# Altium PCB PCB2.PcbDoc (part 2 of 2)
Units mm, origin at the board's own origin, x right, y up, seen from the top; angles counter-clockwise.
Board outline 153.67 x 113.03 mm, 4 copper layers (Top Layer, Mid Layer 1, Mid Layer 2, Bottom Layer), stack 1.57 mm thick; 123 components, 293 nets, 917 pads, 135 vias.
Unrouted connection lines stored in the file: 517.
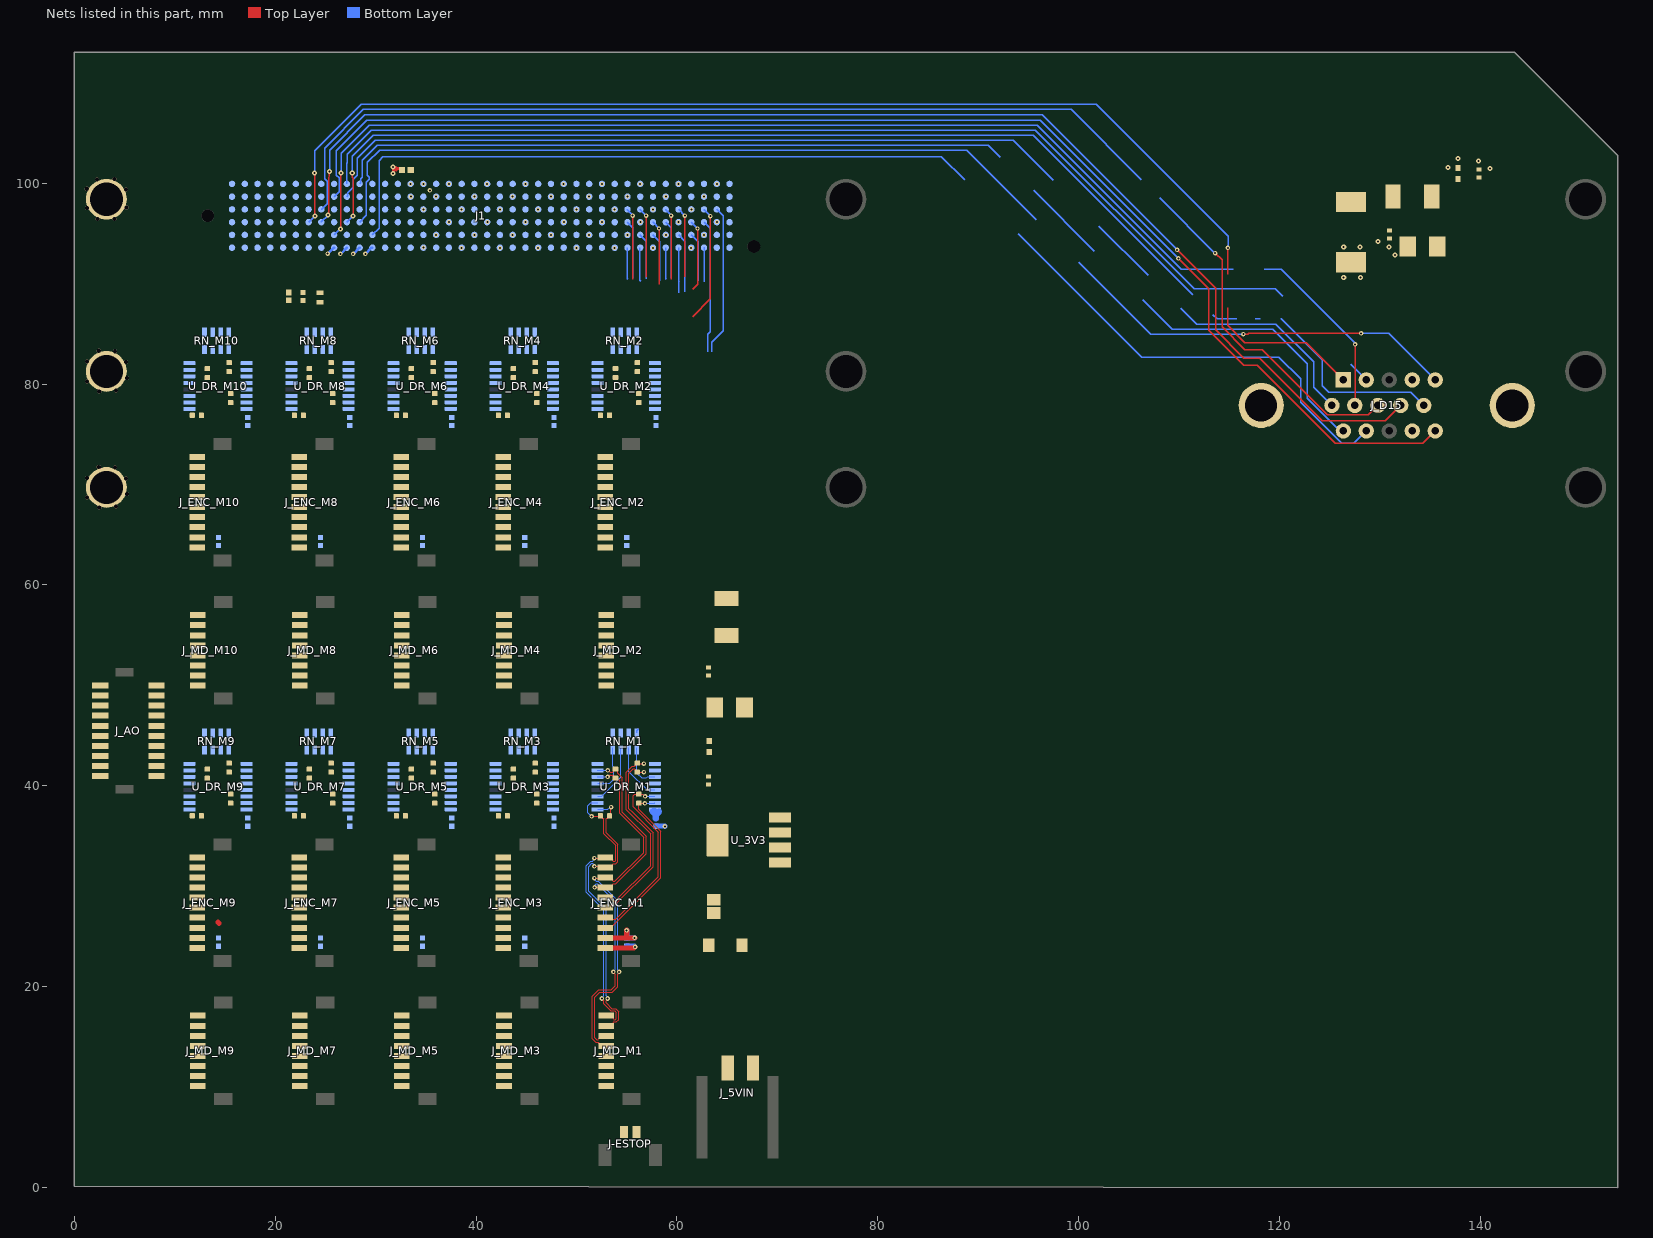
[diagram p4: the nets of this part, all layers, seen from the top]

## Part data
C1: library part CMP-2000-07305-1, "Low ESR, 330 uF, 6.3 V, +/- 10%, -55 to 125 degC, 2-Pin SMD, RoHS, Tape and Reel", Capacitance=330000000pF, Case Code=D, Case Style=Molded, Manufacturer=AVX, Operating Temp Range=-55Cto125C, Package / Case=7343-31, Package Description="2-Pin Surface Mount Device, Body 7.3 x 4.35 mm", Package Reference=CAPMP7344X31-T, Tolerance (+ or -)=10%, Voltage=6.3VDC
C2: library part CMP-2008-04549-2, "Chip Multilayer Ceramic Capacitors for General Purpose, 0402, 4.7uF, X5R, 15%, 20%, 6.3V", Capacitance=4.7uF, Case Code (Imperial)=0402, Case Code (Metric)=1005, Dielectric=X5R, Max Operating Temperature=85°C, Min Operating Temperature=-55°C, Package Quantity=10000, Tolerance=20%, Voltage=6.3V
C5_1: library part CMP-2008-02081-2, "CAP CER 1UF 10V X5R 0402", Capacitance=1uF, Case Code (Imperial)=0402, Case Code (Metric)=1005, Dielectric=X5R, Dielectric Material=Ceramic, Max Operating Temperature=85°C, Min Operating Temperature=-55°C, Package Quantity=1, Tolerance=10%, Voltage=10V
C5_2: library part CMP-13271-000002-1, "CAP CER 10UF 10V X5R 0402", Capacitance=10uF, Manufacturer=Samsung, Temperature="-55°C to +85°C", Temperature Characteristic=X5R, Temperature Coefficient=15%, Temperature Range High=+85°C, Temperature Range Low=-55°C, Tolerance=20%, Voltage Rating=10V
C5_3: library part CMP-2008-02743-1, Manufacturer="AVX Interconnect / Elco"
C10 C11 C50 C51: library part CMP-2100-03641-2, "CAP CER 0.1UF 16V X7R 0402", Capacitance=0.10μF, Manufacturer=Murata, Package=GRM15, Temperature="-55°C to +125°C", Temperature Characteristic=X7R, Temperature Range High=+125°C, Temperature Range Low=-55°C, Tolerance=10%, Voltage Rating=16Vdc
C12 C52: library part CMP-1662-00011-2, "Chip Capacitor, 100 uF, +/- 20%, 6.3 V, -55 to 85 degC, 1206 (3216 Metric), RoHS, Tape and Reel", Capacitance="100 uF", Case Code (Imperial)=1206, Case Code (Metric)=3216, Max Operating Temperature="85 degC", Min Operating Temperature="-55 degC", Package Quantity=2000, Tolerance=20%, Type (Capacitors)=X5R, Voltage Rating="6.3 V"
C13 C53: library part CMP-2008-02797-2, "General Purpose Ceramic Capacitor, 0402, 10nF, 10%, X7R, 15%, 16V", Capacitance=10nF, Case Code (Imperial)=0402, Case Code (Metric)=1005, Dielectric=X7R, Insulation Resistance=100GR, Max Operating Temperature=125°C, Min Operating Temperature=-55°C, Package Quantity=1, Tolerance=10%, Voltage=16V
C60: library part CMP-08246-002634-1, "CAP CER 68UF 10V X5R 1206", Capacitance=68uF, Case Code (Imperial)=1206, Case Code (Metric)=3216, Dielectric=X5R, Dielectric Material=Ceramic, Max Operating Temperature=85°C, Min Operating Temperature=-55°C, Package Quantity=2000, Tolerance=20%, Voltage Rating=10V
C61: library part CMP-08246-003796-1, "Multilayer Ceramic Capacitors 33μF ±20% 6.3V X5R SMD 0805", Capacitance=33uF, Case Code (Imperial)=0805, Case Code (Metric)=2012, Dielectric=X5R, Dielectric Material=Ceramic, Max Operating Temperature=85°C, Min Operating Temperature=-55°C, Package Quantity=1, Tolerance=20%, Voltage Rating=6.3V
CP1_M1 CP1_M2 CP1_M3 CP1_M4 CP1_M5 CP1_M6 CP1_M7 CP1_M8 CP1_M9 CP1_M10 CP2_M1 CP2_M2 CP2_M3 CP2_M4 CP2_M5 CP2_M6 CP2_M7 CP2_M8 CP2_M9 CP2_M10: library part CMP-2008-02046-2, "CAP CER 0.1UF 10V X5R 0402", Capacitance="0.10 μF", Manufacturer=Kemet, Package=C0402-BB, Temperature="-55°C to +125°C", Temperature Characteristic=X5R, Temperature Coefficient=15%, Temperature Range High=+125°C, Temperature Range Low=-55°C, Tolerance=0.1, Voltage Rating="10 V"
J1: library part CMP-02761-000136-1, "CONN HD ARRAY PLUG 240P SMD GOLD", Contact Resistance=5.5mR, Housing Color=Black, Max Current Rating=2.3A, Max Operating Temperature=125°C, Max Voltage Rating (AC)=240V, Min Operating Temperature=-55°C
J-ESTOP: library part CMP-04776-000017-1, "CONN HEADER SMD R/A 2POS 1.25MM", Ambient Temperature Range High=+105°C, Ambient Temperature Range Low=-40°C, Current Rating=1.5A, Manufacturer=Molex, Package=HDR2, Temperature="-40°C to +105°C", Voltage Rating=50V
J_5VIN: "No Description Available", Mfr_Name="Molex Connector Corporation"
J_AO: library part CMP-04776-000294-1, "CONN HEADER SMD 20POS 1MM", Color=Natural, Contact Resistance=20mR, Current Rating=1A, Max Operating Temperature=85°C, Min Operating Temperature=-40°C, Package Quantity=1100, Voltage Rating=50V
J_D15: library part "D-Sub 15 Male-2"
J_ENC_M1 J_ENC_M2 J_ENC_M3 J_ENC_M4 J_ENC_M5 J_ENC_M6 J_ENC_M7 J_ENC_M8 J_ENC_M9 J_ENC_M10: library part CMP-003-000001-2, "No Description Available", Mfr_Name="Molex Connector Corporation"
J_MD_M1 J_MD_M2 J_MD_M3 J_MD_M4 J_MD_M5 J_MD_M6 J_MD_M7 J_MD_M8 J_MD_M9 J_MD_M10: library part CMP-005-000000-1, "No Description Available", Mfr_Name="Molex Connector Corporation"
L10 L50: library part CMP-1353-00039-1, "SMD Power Inductor WE-LHMI, L=6.8 µH", Inductance="6.8 ÂµH", Manufacturer="Wuerth Elektronik"
R1_M1 R1_M2 R1_M3 R1_M4 R1_M5 R1_M6 R1_M7 R1_M8 R1_M9 R1_M10 R2_M1 R2_M2 R2_M3 R2_M4 R2_M5 R2_M6 R2_M7 R2_M8 R2_M9 R2_M10 R3_M1 R3_M2 R3_M3 R3_M4 R3_M5 R3_M6 R3_M7 R3_M8 R3_M9 R3_M10 R4_M1 R4_M2 R4_M3 R4_M4 R4_M5 R4_M6 R4_M7 R4_M8 R4_M9 R4_M10: library part CMP-009-00167-3, "Chip Resistor, 100 Ohms, +/-1 %, 63 mW, -55 to 155 degC, 0402", Case/Package=0402, Max Operating Temperature=155°C, Min Operating Temperature=-55°C, Power=63mW, Tolerance=1%
RN_M1 RN_M2 RN_M3 RN_M4 RN_M5 RN_M6 RN_M7 RN_M8 RN_M9 RN_M10: library part CMP-06828-000004-1, "RES ARRAY 4 RES 47 OHM 1206", Case/Package=Molded, Max Operating Temperature=125°C, Min Operating Temperature=-55°C, Number of Resistors=4, Package Quantity=5000, Power Dissipation=63mW, Resistance=47R, Temperature Coefficient=200ppm/°C, Tolerance=5%, Working Voltage=50V
U_3V3: library part CMP-0062-01662-3, "1.5A Fast Ultra Low Dropout Linear Regulator, 5-pin SOT-223, Pb-Free", Manufacturer="Texas Instruments", PackageTopMarking=XYTT*LBEB, PowerWise=N
U_DR_M1 U_DR_M2 U_DR_M3 U_DR_M4 U_DR_M5 U_DR_M6 U_DR_M7 U_DR_M8 U_DR_M9 U_DR_M10: library part CMP-0310-00537-3, "Low-Voltage High-Speed Quadruple Differential Line Receiver with +/-15-kV IEC ESD, 0 TX / 4 RX, 3.3V, -40 to 85 degC, 16-Pin TSSOP (PW), Green(RoHS & no Sb/Br)", Manufacturer="Texas Instruments", Rating=Catalog, Receivers Per Package=4, Supply Voltage(s)(Max)(V)=3.6, Supply Voltage(s)(Min)(V)=3, Supply Voltage(s)(V)=3.3

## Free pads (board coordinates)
  round 4.064 hole 3.3: " "(3.2,69.7) " "(3.2,81.26) " "(3.2,98.4) " "(76.835,69.7) " "(76.835,81.26) " "(76.835,98.4) " "(150.47,69.7) " "(150.47,81.26) " "(150.47,98.4)

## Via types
v1: diameter 0.4, hole 0.2, Top Layer to Bottom Layer, 52 vias
v2: diameter 0.45, hole 0.2, Top Layer to Bottom Layer, 38 vias
v3: diameter 0.4, hole 0.4, Top Layer to Bottom Layer, 24 vias
v4: diameter 0.5, hole 0.2, Top Layer to Bottom Layer, 21 vias

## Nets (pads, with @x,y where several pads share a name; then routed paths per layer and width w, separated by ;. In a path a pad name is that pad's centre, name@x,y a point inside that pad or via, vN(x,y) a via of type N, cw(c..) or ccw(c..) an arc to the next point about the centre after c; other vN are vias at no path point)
3.3V_EXT: C61.1 CP2_M1.1 CP2_M2.1 CP2_M3.1 CP2_M4.1 CP2_M5.1 CP2_M6.1 CP2_M7.1 CP2_M8.1 CP2_M9.1 CP2_M10.1 U_3V3.3 U_3V3.4 U_DR_M1.16 U_DR_M2.16 U_DR_M3.16 U_DR_M4.16 U_DR_M5.16 U_DR_M6.16 U_DR_M7.16 U_DR_M8.16 U_DR_M9.16 U_DR_M10.16 | length 3.2
  Bottom Layer w0.635: CP2_M1.1@57.912,36.779 57.912,37.135 ; U_DR_M1.16@57.636,37.469 U_DR_M1.16@57.803,37.469 ; U_DR_M1.16@57.636,37.469 U_DR_M1.16@57.803,37.469 ; U_DR_M1.16@57.636,37.469 U_DR_M1.16@57.803,37.469 ; U_DR_M1.16@57.636,37.469 U_DR_M1.16@57.803,37.469 ; U_DR_M1.16@57.636,37.469 57.607,37.44 57.912,37.135 ; 57.912,37.135 58.217,37.44 ; 57.912,37.135 58.217,37.44 ; 57.912,37.135 58.217,37.44 ; 57.912,37.135 58.217,37.44
3.3V_RMC: J1.F8
5V_C_SERIES: C1.1 C2.1 C10.2 J1.A16 J1.B15 L10.1
  other v1: 34.747,99.924
  other v2: 33.503,98.654
5V_EXT: C50.2 J_5VIN.1 L50.1
5V_FILT: C11.2 C12.2 C13.1 J_D15.4 L10.2
5V_M1: C51.2 C52.2 C53.1 C60.1 CP1_M1.1 CP1_M2.1 CP1_M3.1 CP1_M4.1 CP1_M5.1 CP1_M6.1 CP1_M7.1 CP1_M8.1 CP1_M9.1 CP1_M10.1 J_ENC_M1.9 J_ENC_M2.9 J_ENC_M3.9 J_ENC_M4.9 J_ENC_M5.9 J_ENC_M6.9 J_ENC_M7.9 J_ENC_M8.9 J_ENC_M9.9 J_ENC_M10.9 L50.2 U_3V3.1 U_3V3.2 | length 10.7
  Top Layer w0.508: 14.3,26.416 14.405,26.311 ; 54.026,24.863 J_ENC_M1.9@52.885,24.863 ; v2(55.004,25.616) 55.004,24.917 54.949,24.863 ; v2@55.787,24.863 54.949,24.863 ; v2@55.799,24.851 v2@55.803,24.855 ; J_ENC_M1.9@52.885,24.863 54.949,24.863 ; J_ENC_M1.9@52.885,24.863 54.949,24.863 ; J_ENC_M1.9@52.885,24.863 54.949,24.863
  Bottom Layer w0.508: CP1_M1.1@55.01,24.841 CP1_M1.1@55.016,24.841 ; v2@55.016,25.604 CP1_M1.1@55.016,24.841 ; v2(55.791,24.867) 55.765,24.841 CP1_M1.1@55.016,24.841 ; CP1_M1.1@55.016,24.823 CP1_M1.1@55.016,24.841 ; CP1_M1.1@55.016,24.823 CP1_M1.1@55.016,24.841 ; CP1_M1.1@55.016,24.823 CP1_M1.1@55.022,24.829 ; CP1_M1.1@55.016,24.823 CP1_M1.1@55.022,24.829 ; CP1_M1.1@55.016,24.823 CP1_M1.1@55.022,24.829 ; CP1_M1.1@55.016,24.823 CP1_M1.1@55.016,24.841
5V_RMC: C5_1.1 C5_2.1 C5_3.2 J1.F9 J1.F10 J1.F11 J1.F12 | length 3.6
  Bottom Layer w0.254: v2(25.222,92.989) 25.254,92.989 25.838,93.574 J1.F9@25.87,93.574 ; v2(26.492,92.964) 26.531,92.964 J1.F10@27.14,93.574 ; v2(27.762,92.964) 27.801,92.964 J1.F11@28.41,93.574 ; v2(28.981,92.964) 29.591,93.574 J1.F12@29.68,93.574
A1: J1.C39 RN_M1.8 | length 16.5
  Bottom Layer w0.142: RN_M1.8@56.007,45.276 RN_M1.8@56.007,45.49 ; RN_M1.8@56.161,45.644 RN_M1.8@56.007,45.49 ; RN_M1.8@56.161,45.655 56.007,45.5 RN_M1.8@56.007,45.49 ; 63.475,83.219 63.475,84.176 64.605,85.306 64.605,89.027 64.605,96.749 ; 64.605,96.749 J1.C39@63.97,97.384 64.605,96.749
A2: J1.C38 RN_M2.8 | length 11.7
  Top Layer w0.142: 61.567,86.713 63.322,88.468 63.322,91.275 63.322,96.215 v2(63.322,96.723)
  Bottom Layer w0.142: J1.C38@62.624,97.308 J1.C38@62.624,97.314 ; J1.C38@62.7,97.384 62.7,97.364 63.322,96.743 v2(63.322,96.723)
A3: J1.C36 RN_M3.8 | length 7
  Top Layer w0.142: 60.757,90.678 60.782,90.703 v2(60.782,96.761)
  Bottom Layer w0.142: J1.C36@60.16,97.384 v2(60.782,96.761)
A4: J1.C35 RN_M4.8 | length 7.2
  Top Layer w0.142: 59.436,90.424 v2(59.436,96.774)
  Bottom Layer w0.142: J1.C35@58.89,97.384 58.89,97.352 59.436,96.806 v2(59.436,96.774)
A5: J1.C33 RN_M5.8 | length 9.6
  Top Layer w0.142: 56.921,90.678 56.947,90.703 v2(56.947,96.761)
  Bottom Layer w0.142: J1.C33@56.325,97.383 v2(56.947,96.761) ; J1.C33@56.325,97.383 v2(56.947,96.761) ; J1.C33@56.325,97.383 v2(56.947,96.761) ; J1.C33@56.325,97.383 v2(56.947,96.761)
A6: J1.C30 RN_M6.8
A7: J1.C32 RN_M7.8 | length 7.3
  Top Layer w0.142: 55.601,90.424 v2(55.601,96.774)
  Bottom Layer w0.142: v2(55.601,96.774) 55.601,96.806 J1.C32@55.055,97.352 ; J1.C32@55.055,97.352 J1.C32@55.055,97.384 ; J1.C32@55.055,97.352 J1.C32@55.055,97.384 ; J1.C32@55.055,97.352 J1.C32@55.055,97.384 ; J1.C32@55.055,97.352 J1.C32@55.055,97.384
A8: J1.C29 RN_M8.8
A9: J1.C27 RN_M9.8
A10: J1.C26 RN_M10.8
A_M1_N: J_ENC_M1.6 R3_M1.2 U_DR_M1.9 | length 18.7
  Top Layer w0.114: J_ENC_M1.6@52.897,27.851 J_ENC_M1.6@53.372,27.851 ; J_ENC_M1.6@53.36,27.863 J_ENC_M1.6@53.603,28.106 ; 53.603,28.175 J_ENC_M1.6@53.603,28.106 ; 53.924,28.242 57.62,31.939 57.62,35.329 55.53,37.42 55.213,37.737 55.213,41.237 55.656,41.68 55.773,41.68 55.843,41.61 55.843,41.544 56.036,41.351 R3_M1.2@56.058,41.351 ; 53.936,28.23 53.682,28.23 53.615,28.163 J_ENC_M1.6@53.603,28.106 ; R3_M1.2@56.07,41.364 v2(56.718,41.364) ; R3_M1.2@56.07,41.339 R3_M1.2@56.082,41.352 ; R3_M1.2@56.07,41.339 R3_M1.2@56.082,41.352 ; R3_M1.2@56.07,41.339 R3_M1.2@56.082,41.352 ; R3_M1.2@56.07,41.339 R3_M1.2@56.082,41.352
A_M1_P: J_ENC_M1.5 R3_M1.1 U_DR_M1.10 | length 18.6
  Top Layer w0.114: J_ENC_M1.5@52.897,28.851 J_ENC_M1.5@53.372,28.851 ; J_ENC_M1.5@53.36,28.863 J_ENC_M1.5@53.372,28.851 ; 53.67,28.484 53.824,28.484 57.379,32.039 57.379,35.229 54.971,37.637 54.971,41.337 55.556,41.922 55.773,41.922 55.843,41.992 55.843,42.059 56.036,42.251 R3_M1.1@56.058,42.251 ; 53.682,28.472 53.615,28.539 53.603,28.551 53.603,28.62 J_ENC_M1.5@53.372,28.851 ; R3_M1.1@56.07,42.239 R3_M1.1@56.119,42.19 ; R3_M1.1@56.107,42.202 v2(56.706,42.202)
A_M2_N: J_ENC_M2.6 R3_M2.2 U_DR_M2.9
A_M2_P: J_ENC_M2.5 R3_M2.1 U_DR_M2.10
A_M3_N: J_ENC_M3.6 R3_M3.2 U_DR_M3.9
A_M3_P: J_ENC_M3.5 R3_M3.1 U_DR_M3.10
A_M4_N: J_ENC_M4.6 R3_M4.2 U_DR_M4.9
A_M4_P: J_ENC_M4.5 R3_M4.1 U_DR_M4.10
A_M5_N: J_ENC_M5.6 R3_M5.2 U_DR_M5.9
A_M5_P: J_ENC_M5.5 R3_M5.1 U_DR_M5.10
A_M6_N: J_ENC_M6.6 R3_M6.2 U_DR_M6.9
A_M6_P: J_ENC_M6.5 R3_M6.1 U_DR_M6.10
A_M7_N: J_ENC_M7.6 R3_M7.2 U_DR_M7.9
A_M7_P: J_ENC_M7.5 R3_M7.1 U_DR_M7.10
A_M8_N: J_ENC_M8.6 R3_M8.2 U_DR_M8.9
A_M8_P: J_ENC_M8.5 R3_M8.1 U_DR_M8.10
A_M9_N: J_ENC_M9.6 R3_M9.2 U_DR_M9.9
A_M9_P: J_ENC_M9.5 R3_M9.1 U_DR_M9.10
A_M10_N: J_ENC_M10.6 R3_M10.2 U_DR_M10.9
A_M10_P: J_ENC_M10.5 R3_M10.1 U_DR_M10.10
AGND: J_AO.1 J_AO.2 J_AO.3 J_AO.4 J_AO.5 J_AO.6 J_AO.7 J_AO.8 J_AO.9 J_AO.10
AGND_M1: J_MD_M1.8 J_MD_M2.8 J_MD_M3.8 J_MD_M4.8 J_MD_M5.8 J_MD_M6.8 J_MD_M7.8 J_MD_M8.8 J_MD_M9.8 J_MD_M10.8
ANA1: J_AO.12 J_MD_M1.7
ANA2: J_AO.11 J_MD_M2.7
ANA3: J_AO.14 J_MD_M3.7
ANA4: J_AO.13 J_MD_M4.7
ANA5: J_AO.16 J_MD_M5.7
ANA6: J_AO.15 J_MD_M6.7
ANA7: J_AO.18 J_MD_M7.7
ANA8: J_AO.17 J_MD_M8.7
ANA9: J_AO.20 J_MD_M9.7
ANA10: J_AO.19 J_MD_M10.7
B1: J1.D38 RN_M1.7 | length 13.3
  Bottom Layer w0.142: J1.D38@62.7,96.114 63.309,95.505 63.309,85.395 63.309,85.179 63.068,84.938 63.068,83.21
B2: J1.D37 RN_M2.7 | length 7.1
  Top Layer w0.142: 61.582,89.459 62.065,89.941 v1(62.065,95.479)
  Bottom Layer w0.142: J1.D37@61.43,96.114 v1(62.065,95.479)
B3: J1.D35 RN_M3.7 | length 5.8
  Bottom Layer w0.142: J1.D35@58.89,96.114 59.436,95.568 59.436,90.551
B4: J1.D34 RN_M4.7 | length 6.6
  Top Layer w0.142: 58.229,89.941 v1(58.229,95.479)
  Bottom Layer w0.142: J1.D34@57.62,96.082 J1.D34@57.62,96.088 ; J1.D34@57.62,96.114 J1.D34@57.62,96.088 ; v1(58.229,95.479) J1.D34@57.62,96.088 ; J1.D34@57.595,96.113 J1.D34@57.62,96.088 ; J1.D34@57.595,96.113 J1.D34@57.62,96.088 ; J1.D34@57.595,96.113 J1.D34@57.62,96.088 ; J1.D34@57.595,96.113 J1.D34@57.62,96.088
B5: J1.D32 RN_M5.7 | length 8.1
  Bottom Layer w0.142: 55.601,90.551 55.601,95.568 ; J1.D32@55.055,96.114 55.601,95.568 ; J1.D32@55.055,96.114 55.601,95.568 ; J1.D32@55.055,96.114 55.601,95.568 ; J1.D32@55.055,96.114 55.601,95.568
B6: J1.D31 RN_M6.7
B7: J1.D29 RN_M7.7
B8: J1.D28 RN_M8.7
B9: J1.D26 RN_M9.7
B10: J1.D25 RN_M10.7
B_M1_N: J_ENC_M1.8 R4_M1.2 U_DR_M1.15 | length 17.5
  Top Layer w0.114: J_ENC_M1.8@52.885,25.863 53.128,26.106 53.651,26.106 58.408,30.863 58.408,35.477 56.21,37.674 R4_M1.2@56.21,38.267 56.225,38.252 v2(56.82,38.252)
  Bottom Layer w0.114: v2(56.82,38.252) 56.839,38.272 57.784,38.272 U_DR_M1.15@57.803,38.291
B_M1_P: J_ENC_M1.7 R4_M1.1 U_DR_M1.14 | length 18.5
  Top Layer w0.114: J_ENC_M1.7@52.885,26.863 53.061,26.687 53.891,26.687 58.166,30.963 58.166,35.377 55.651,37.891 55.651,39.014 55.804,39.167 R4_M1.1@56.21,39.167 56.617,39.167 v2(56.845,38.938)
  Bottom Layer w0.114: v2(56.845,38.938) 56.847,38.94 57.801,38.94 U_DR_M1.14@57.803,38.941
B_M2_N: J_ENC_M2.8 R4_M2.2 U_DR_M2.15
B_M2_P: J_ENC_M2.7 R4_M2.1 U_DR_M2.14
B_M3_N: J_ENC_M3.8 R4_M3.2 U_DR_M3.15
B_M3_P: J_ENC_M3.7 R4_M3.1 U_DR_M3.14
B_M4_N: J_ENC_M4.8 R4_M4.2 U_DR_M4.15
B_M4_P: J_ENC_M4.7 R4_M4.1 U_DR_M4.14
B_M5_N: J_ENC_M5.8 R4_M5.2 U_DR_M5.15
B_M5_P: J_ENC_M5.7 R4_M5.1 U_DR_M5.14
B_M6_N: J_ENC_M6.8 R4_M6.2 U_DR_M6.15
B_M6_P: J_ENC_M6.7 R4_M6.1 U_DR_M6.14
B_M7_N: J_ENC_M7.8 R4_M7.2 U_DR_M7.15
B_M7_P: J_ENC_M7.7 R4_M7.1 U_DR_M7.14
B_M8_N: J_ENC_M8.8 R4_M8.2 U_DR_M8.15
B_M8_P: J_ENC_M8.7 R4_M8.1 U_DR_M8.14
B_M9_N: J_ENC_M9.8 R4_M9.2 U_DR_M9.15
B_M9_P: J_ENC_M9.7 R4_M9.1 U_DR_M9.14
B_M10_N: J_ENC_M10.8 R4_M10.2 U_DR_M10.15
B_M10_P: J_ENC_M10.7 R4_M10.1 U_DR_M10.14
CVRT_DIO3: J1.D8 J_D15.9 | length 131.3
  Top Layer w0.142: v4(25.265,96.85) 25.32,96.905 25.32,100.609 25.39,100.68 25.39,101.105 v4(25.428,101.143) ; v2(109.804,93.345) 113.64,89.51 113.64,85.395 116.459,82.575 118.008,82.575 124.257,76.327 130.524,76.327 J_D15.9@132.067,77.87
  Bottom Layer w0.142: J1.D8@24.6,96.114 24.6,96.15 25.265,96.814 v4(25.265,96.85) ; v4(25.428,101.143) 25.428,103.28 28.936,106.788 96.362,106.788 v2(109.804,93.345)
D15_P1: J1.D7 J_D15.1 | length 125.1
  Top Layer w0.142: v4(23.927,100.99) 23.952,100.965 23.952,96.774 v4(23.978,96.749) ; 114.833,87.605 114.833,85.831 116.54,84.125 122.637,84.125 J_D15.1@126.352,80.41 ; 114.833,90.932 114.833,93.523 v2(114.859,93.548)
  Bottom Layer w0.142: J1.D7@23.33,96.114 23.337,96.114 23.972,96.749 v4(23.978,96.749) ; v4(23.927,100.99) 23.927,103.219 28.561,107.852 101.774,107.852 106.934,102.692 114.892,94.734 114.892,93.582 v2(114.859,93.548)
D15_P2: J1.A10 J_D15.2 | length 106.2
  Bottom Layer w0.142: J1.A10@27.14,99.924 27.14,101.981 27.175,102.016 27.175,102.895 29.56,105.28 95.686,105.28 111.482,89.484 119.564,89.484 120.313,88.735 ; 127.079,81.969 J_D15.2@128.638,80.41
D15_P5: J1.D11 J_D15.5 | length 116.8
  Top Layer w0.142: v2(116.407,84.968) 116.845,84.968 116.915,85.039 v2(128.118,85.039)
  Bottom Layer w0.142: J1.D11@28.41,96.114 29.083,96.786 29.083,100.101 29.362,100.381 29.362,100.585 29.185,100.763 29.185,102.063 30.393,103.271 88.855,103.271 95.771,96.355 ; 99.987,92.138 107.168,84.957 116.396,84.957 v2(116.407,84.968) ; v2(128.118,85.039) 130.886,85.039 135.496,80.429 J_D15.5@135.496,80.41
D15_P6: J1.B10 J_D15.6 | length 103.4
  Bottom Layer w0.142: J1.B10@27.14,98.654 27.228,98.741 27.228,99.036 27.762,99.57 27.762,100.39 28.18,100.808 28.18,102.479 29.976,104.276 93.463,104.276 97.447,100.292 ; 102.019,95.72 106.934,90.805 ; 110.185,87.554 111.766,85.973 119.64,85.973 123.419,82.194 123.419,79.66 J_D15.6@125.209,77.87
D15_P7: J1.E9 J_D15.7 | length 122.7
  Top Layer w0.142: v4(26.492,95.453) 26.53,95.491 26.53,100.978 v4(26.568,101.016) ; J_D15.7@127.495,77.87 127.514,77.889 127.514,83.928 v2(127.533,83.947)
  Bottom Layer w0.142: J1.E9@25.87,94.844 25.877,94.844 26.486,95.453 v4(26.492,95.453) ; v4(26.568,101.016) 26.568,102.999 29.352,105.783 95.894,105.783 110.237,91.44 115.392,91.44 ; 118.466,91.44 120.167,91.44 127.432,84.176 127.432,84.132 127.533,84.03 v2(127.533,83.947)
D15_P8: J1.C8 J_D15.8 | length 127.3
  Top Layer w0.142: v2(113.589,93.04) 114.277,92.352 114.277,85.677 116.532,83.423 118.265,83.423 124.768,76.92 128.85,76.92 129.781,77.851 J_D15.8@129.781,77.87
  Bottom Layer w0.142: J1.C8@24.6,97.384 24.619,97.384 25.172,97.936 25.172,100.188 24.926,100.434 24.926,103.488 28.788,107.35 99.254,107.35 106.248,100.355 ; 108.064,98.539 113.563,93.04 v2(113.589,93.04)
D15_P10: J1.D10 J_D15.10 | length 120.3
  Top Layer w0.142: v4(27.677,101.016) 27.691,101.002 27.691,100.553 27.762,100.482 v4(27.762,96.749)
  Bottom Layer w0.142: J1.D10@27.14,96.114 27.14,96.12 27.762,96.742 v4(27.762,96.749) ; v4(27.677,101.016) 27.677,102.687 29.768,104.778 95.478,104.778 111.355,88.901 ; 113.361,86.894 113.78,86.476 115.722,86.476 ; 117.602,86.476 118.085,86.476 ; 120.142,86.476 120.179,86.476 124.244,82.41 124.244,79.845 124.917,79.172 133.051,79.172 J_D15.10@134.353,77.87
D15_P11: J1.A11 J_D15.11 | length 103.1
  Bottom Layer w0.142: J1.A11@28.41,99.924 28.506,100.019 28.506,100.423 28.682,100.6 28.682,102.271 30.184,103.773 91.019,103.773 92.215,102.578 ; 95.504,99.289 101.562,93.231 ; 106.388,88.405 109.322,85.471 119.304,85.471 122.758,82.017 122.758,78.588 126.016,75.33 J_D15.11@126.352,75.33
D15_P12: J1.E12 J_D15.12 | length 112.2
  Bottom Layer w0.142: J1.E12@29.68,94.844 30.355,95.518 30.355,102.237 30.734,102.616 86.335,102.616 88.633,100.317 ; 94.005,94.945 106.274,82.677 119.939,82.677 122.098,80.518 122.098,78.181 126.187,74.092 127.4,74.092 J_D15.12@128.638,75.33
D15_P15: J1.B9 J_D15.15 | length 131.8
  Top Layer w0.142: v2(109.931,92.507) 112.954,89.484 112.954,85.367 116.431,81.89 117.76,81.89 125.558,74.092 134.258,74.092 J_D15.15@135.496,75.33
  Bottom Layer w0.142: J1.B9@25.87,98.654 26.363,99.146 26.363,100.511 26.066,100.808 26.066,103.207 29.144,106.285 96.153,106.285 v2(109.931,92.507)
DIO0: J1.F38 RN_M1.5 | length 13.5
  Bottom Layer w0.142: 62.725,90.195 62.7,90.221 ; 62.7,90.221 J1.F38@62.7,93.574 ; 62.7,90.221 J1.F38@62.7,93.574 ; 62.7,90.221 J1.F38@62.7,93.574 ; 62.7,90.221 J1.F38@62.7,93.574 ; J1.F38@62.7,93.574 J1.F38@62.7,93.599 ; J1.F38@62.7,93.574 J1.F38@62.7,93.599 ; J1.F38@62.7,93.574 J1.F38@62.7,93.599 ; J1.F38@62.7,93.574 J1.F38@62.7,93.599
DIO1: J1.F36 RN_M2.5 | length 4.6
  Bottom Layer w0.142: 60.16,89.099 60.16,90.322 ; J1.F36@60.16,93.574 60.16,90.322 ; 60.236,90.246 60.16,90.322
DIO2: J1.F35 RN_M3.5 | length 3.2
  Bottom Layer w0.142: J1.F35@58.89,93.574 58.89,90.462 58.928,90.424
DIO3: J1.F33 RN_M4.5 | length 13.1
  Bottom Layer w0.142: 56.401,90.246 56.325,90.322 ; 56.325,90.322 J1.F33@56.325,93.574 ; 56.325,90.322 J1.F33@56.325,93.574 ; 56.325,90.322 J1.F33@56.325,93.574 ; 56.325,90.322 J1.F33@56.325,93.574
DIO4: J1.F32 RN_M5.5 | length 12.5
  Bottom Layer w0.142: 55.093,90.424 55.055,90.462 ; 55.055,90.462 J1.F32@55.055,93.574 ; 55.055,90.462 J1.F32@55.055,93.574 ; 55.055,90.462 J1.F32@55.055,93.574 ; 55.055,90.462 J1.F32@55.055,93.574
DIO5: J1.F30 RN_M6.5
DIO6: J1.F29 RN_M7.5
DIO7: J1.F27 RN_M8.5
DIO8: J1.F26 RN_M9.5
DIO9: J1.F24 RN_M10.5
DIO10: J1.F23
DIO11: J1.F21
DIO12: J1.F20
DIO13: J1.F18
DIO14: J1.F17
DIO15: J1.F15
DIO26: J1.C24
DIO27: J1.C23
DIO28: J1.C21
DIO29: J1.C20
DIO30: J1.C18
DIO31: J1.C17
DIO32: J1.E37 RN_M1.6 | length 4.8
  Bottom Layer w0.142: J1.E37@61.43,94.844 62.103,94.171 62.103,90.278
DIO33: J1.E36 RN_M2.6 | length 5.9
  Bottom Layer w0.142: J1.E36@60.16,94.844 60.795,94.209 60.795,90.5 60.795,89.192
DIO34: J1.E34 RN_M3.6 | length 7.7
  Bottom Layer w0.142: 58.268,90.278 58.268,94.171 ; J1.E34@57.595,94.844 58.268,94.171 ; J1.E34@57.595,94.844 58.268,94.171 ; J1.E34@57.595,94.844 58.268,94.171 ; J1.E34@57.595,94.844 58.268,94.171
DIO35: J1.E33 RN_M4.6 | length 7.3
  Bottom Layer w0.142: 56.959,90.5 56.959,94.209 ; J1.E33@56.325,94.844 56.959,94.209 ; J1.E33@56.325,94.844 56.959,94.209 ; J1.E33@56.325,94.844 56.959,94.209 ; J1.E33@56.325,94.844 56.959,94.209
DIO36: J1.E31 RN_M5.6
DIO37: J1.E30 RN_M6.6
DIO38: J1.E28 RN_M7.6
DIO39: J1.E27 RN_M8.6
DIO40: J1.E25 RN_M9.6
DIO41: J1.E24 RN_M10.6
DIO42: J1.E22
DIO43: J1.E21
DIO44: J1.E19
DIO45: J1.E18
DIO46: J1.E16
DIO47: J1.E15
DIO48: J1.B39
DIO49: J1.B37
DIO50: J1.B36
DIO51: J1.B34
DIO52: J1.B33
DIO53: J1.B31
DIO54: J1.B30
DIO55: J1.B28
DIO56: J1.B27
DIO57: J1.B25
DIO58: J1.B24
DIO59: J1.B22
DIO60: J1.B21
DIO61: J1.B19
DIO62: J1.B18
DIO63: J1.B16
DIO74: J1.D23
DIO75: J1.D22
DIO76: J1.D20
DIO77: J1.D19
DIO78: J1.D17
DIO79: J1.D16
DIO80: J1.A40
DIO81: J1.A38
DIO82: J1.A37
DIO83: J1.A35
DIO84: J1.A34
DIO85: J1.A32
DIO86: J1.A31
DIO87: J1.A29
DIO88: J1.A28
DIO89: J1.A26
DIO90: J1.A25
DIO91: J1.A23
DIO92: J1.A22
DIO93: J1.A20
DIO94: J1.A19
DIO95: J1.A17
  other v2: 35.395,99.289
GND: "pad. "@3.2,69.7 "pad. "@3.2,81.26 "pad. "@3.2,98.4 C1.2 C2.2 C5_1.2 C5_2.2 C5_3.1 C10.1 C11.1 C12.1 C13.2 C50.1 C51.1 C52.1 C53.2 C60.2 C61.2 CP1_M1.2 CP1_M2.2 CP1_M3.2 CP1_M4.2 CP1_M5.2 CP1_M6.2 CP1_M7.2 CP1_M8.2 CP1_M9.2 CP1_M10.2 CP2_M1.2 CP2_M2.2 CP2_M3.2 CP2_M4.2 CP2_M5.2 CP2_M6.2 CP2_M7.2 CP2_M8.2 CP2_M9.2 CP2_M10.2 J1.A3 J1.A4 J1.A9 J1.A12 J1.A15 J1.A18 J1.A21 J1.A24 J1.A27 J1.A30 J1.A33 J1.A36 J1.A39 J1.B1 J1.B2 J1.B5 J1.B8 J1.B11 J1.B14 J1.B17 J1.B20 J1.B23 J1.B26 J1.B29 J1.B32 J1.B35 J1.B38 J1.C3 J1.C4 J1.C7 J1.C10 J1.C13 J1.C16 J1.C19 J1.C22 J1.C25 J1.C28 J1.C31 J1.C34 J1.C37 J1.C40 J1.D1 J1.D2 J1.D5 J1.D9 J1.D12 J1.D15 J1.D18 J1.D21 J1.D24 J1.D27 J1.D30 J1.D33 J1.D36 J1.D39 J1.E3 J1.E4 J1.E7 J1.E8 J1.E11 J1.E14 J1.E17 J1.E20 J1.E23 J1.E26 J1.E29 J1.E32 J1.E35 J1.E38 J1.F1 J1.F2 J1.F5 J1.F6 J1.F13 J1.F16 J1.F19 J1.F22 J1.F25 J1.F28 J1.F31 J1.F34 J1.F37 J_5VIN.2 J_D15.14 J_D15.16 J_D15.17 J_ENC_M1.10 J_ENC_M2.10 J_ENC_M3.10 J_ENC_M4.10 J_ENC_M5.10 J_ENC_M6.10 J_ENC_M7.10 J_ENC_M8.10 J_ENC_M9.10 J_ENC_M10.10 U_3V3.5 U_DR_M1.8 U_DR_M1.12 U_DR_M2.8 U_DR_M2.12 U_DR_M3.8 U_DR_M3.12 U_DR_M4.8 U_DR_M4.12 U_DR_M5.8 U_DR_M5.12 U_DR_M6.8 U_DR_M6.12 U_DR_M7.8 U_DR_M7.12 U_DR_M8.8 U_DR_M8.12 U_DR_M9.8 U_DR_M9.12 U_DR_M10.8 U_DR_M10.12 | length 6.9
  Top Layer w0.254: v4@31.75,100.99 v4(31.75,101.6) v4@31.797,101.553 ; v4@31.797,101.186 v4@31.797,101.553 ; 32.01,101.592 32.147,101.454 32.483,101.454 C2.2@32.642,101.295 ; 32.055,101.295 v4@31.797,101.553
  Top Layer w0.508: J_ENC_M1.10@52.897,23.851 55.028,23.851 ; 55.016,23.863 55.74,23.863 v2(55.842,23.965)
  Bottom Layer w0.508: CP1_M1.2@55.004,24.035 55.01,24.029 55.778,24.029 v2(55.842,23.965) ; CP2_M1.2@57.912,35.979 58.788,35.979 v2(58.801,35.966)
  other v1: 34.76,93.574 38.561,93.565 42.371,93.565 46.181,93.565 49.991,93.565 53.801,93.565 57.611,93.565 61.421,93.565 36.03,94.844 39.84,94.844 43.65,94.844 47.46,94.844 51.27,94.844 55.08,94.844 58.89,94.844 62.7,94.844 37.314,96.114 41.124,96.114 44.934,96.114 48.744,96.114 52.554,96.114 56.364,96.114 60.174,96.114 63.97,96.114 34.76,97.384 38.57,97.384 42.38,97.384 46.19,97.384 50,97.384 53.81,97.384 57.62,97.384 61.43,97.384 36.03,98.654 39.84,98.654 43.65,98.654 47.46,98.654 51.27,98.654 55.08,98.654 58.89,98.654 62.7,98.654 33.477,99.924 37.3,99.924 41.11,99.924 44.92,99.924 48.73,99.924 52.54,99.924 56.35,99.924 60.16,99.924 63.97,99.924
  other v3: 2.489,67.716 4.14,67.818 1.27,68.707 5.258,69.037 5.156,70.612 1.27,70.663 4.039,71.704 2.438,71.755 2.489,79.273 4.14,79.375 1.27,80.264 5.258,80.594 5.156,82.169 1.27,82.22 4.039,83.261 2.438,83.312 2.311,96.418 3.988,96.418 1.27,97.511 5.182,97.587 5.156,99.365 1.245,99.441 2.286,100.355 4.013,100.432
  other v4: 126.39,90.627 128.067,90.627 131.47,92.862 126.39,93.624 128.016,93.624 130.912,93.65 129.819,94.183 31.75,100.965 140.97,101.473 136.779,101.549 139.802,102.184 137.77,102.464
MA_M1_N: J_ENC_M1.2 J_MD_M1.2 R1_M1.2 U_DR_M1.1 | length 33.6
  Top Layer w0.114: J_MD_M1.2@52.946,16.106 53.421,16.106 53.664,16.349 53.664,16.419 53.731,16.486 53.985,16.486 54.193,16.694 54.193,17.519 53.892,17.82 53.537,17.82 52.947,18.41 52.947,18.587 53.114,18.754 v2(53.114,18.821) ; v2(53.454,37.871) 53.436,37.853 53.436,37.205 53.454,37.187 53.465,37.198 R1_M1.2@53.465,37.154 ; v2(51.791,31.979) J_ENC_M1.2@53.244,31.979 ; v2(51.791,31.979) J_ENC_M1.2@53.244,31.979 ; v2(51.791,31.979) J_ENC_M1.2@53.244,31.979 ; R1_M1.2@53.096,36.784 R1_M1.2@53.465,37.154 ; R1_M1.2@53.096,36.784 R1_M1.2@53.465,37.154 ; R1_M1.2@53.096,36.784 R1_M1.2@53.465,37.154 ; R1_M1.2@53.096,36.784 53.029,36.784 52.959,36.714 52.959,35.341 54.132,34.168 54.132,32.451 53.924,32.242 53.936,32.23 53.682,32.23 53.615,32.163 53.603,32.175 53.603,32.106 53.36,31.863 J_ENC_M1.2@53.244,31.979
  Bottom Layer w0.114: v2(51.791,31.979) 51.791,32.069 51.677,32.183 51.677,32.197 51.61,32.264 51.515,32.264 51.206,31.955 51.206,29.515 52.947,27.775 52.947,19.08 53.114,18.912 v2(53.114,18.821) ; U_DR_M1.1@52.103,37.641 53.133,37.641 53.364,37.871 v2(53.454,37.871)
MA_M1_P: J_ENC_M1.1 J_MD_M1.1 R1_M1.1 U_DR_M1.2 | length 34.7
  Top Layer w0.114: v2(52.537,18.821) 52.537,18.754 52.705,18.587 52.705,18.31 53.437,17.578 53.792,17.578 53.952,17.419 53.952,16.794 53.885,16.727 53.731,16.727 53.664,16.794 53.664,16.864 53.421,17.106 J_MD_M1.1@52.946,17.106 ; v2(51.511,36.957) R1_M1.1@52.408,36.957 ; v2(51.511,36.957) R1_M1.1@52.408,36.957 ; v2(51.511,36.957) R1_M1.1@52.408,36.957 ; v2(51.791,32.791) J_ENC_M1.1@53.289,32.791 ; v2(51.791,32.791) J_ENC_M1.1@53.289,32.791 ; v2(51.791,32.791) J_ENC_M1.1@53.289,32.791 ; R1_M1.1@52.408,36.957 52.581,36.784 52.647,36.784 52.717,36.714 52.717,35.241 53.891,34.067 53.891,32.551 53.824,32.484 53.67,32.484 53.603,32.551 53.603,32.62 53.36,32.863 J_ENC_M1.1@53.289,32.791
  Bottom Layer w0.114: v2(51.511,36.957) 51.486,36.957 51.127,37.316 51.127,37.411 51.13,37.414 51.13,38.024 51.398,38.291 U_DR_M1.2@52.103,38.291 ; v2(51.791,32.791) 51.791,32.701 51.677,32.587 51.677,32.573 51.61,32.506 51.415,32.506 50.965,32.055 50.965,29.415 52.705,27.675 52.705,19.08 52.537,18.912 v2(52.537,18.821)
MA_M2_N: J_ENC_M2.2 J_MD_M2.2 R1_M2.2 U_DR_M2.1
MA_M2_P: J_ENC_M2.1 J_MD_M2.1 R1_M2.1 U_DR_M2.2
MA_M3_N: J_ENC_M3.2 J_MD_M3.2 R1_M3.2 U_DR_M3.1
MA_M3_P: J_ENC_M3.1 J_MD_M3.1 R1_M3.1 U_DR_M3.2
MA_M4_N: J_ENC_M4.2 J_MD_M4.2 R1_M4.2 U_DR_M4.1
MA_M4_P: J_ENC_M4.1 J_MD_M4.1 R1_M4.1 U_DR_M4.2
MA_M5_N: J_ENC_M5.2 J_MD_M5.2 R1_M5.2 U_DR_M5.1
MA_M5_P: J_ENC_M5.1 J_MD_M5.1 R1_M5.1 U_DR_M5.2
MA_M6_N: J_ENC_M6.2 J_MD_M6.2 R1_M6.2 U_DR_M6.1
MA_M6_P: J_ENC_M6.1 J_MD_M6.1 R1_M6.1 U_DR_M6.2
MA_M7_N: J_ENC_M7.2 J_MD_M7.2 R1_M7.2 U_DR_M7.1
MA_M7_P: J_ENC_M7.1 J_MD_M7.1 R1_M7.1 U_DR_M7.2
MA_M8_N: J_ENC_M8.2 J_MD_M8.2 R1_M8.2 U_DR_M8.1
MA_M8_P: J_ENC_M8.1 J_MD_M8.1 R1_M8.1 U_DR_M8.2
MA_M9_N: J_ENC_M9.2 J_MD_M9.2 R1_M9.2 U_DR_M9.1
MA_M9_P: J_ENC_M9.1 J_MD_M9.1 R1_M9.1 U_DR_M9.2
MA_M10_N: J_ENC_M10.2 J_MD_M10.2 R1_M10.2 U_DR_M10.1
MA_M10_P: J_ENC_M10.1 J_MD_M10.1 R1_M10.1 U_DR_M10.2
NetRN_M1_1: RN_M1.1 U_DR_M1.11 | length 12.3
  Bottom Layer w0.114: U_DR_M1.11@57.803,40.891 57.076,40.891 56.961,40.777 56.475,40.777 56.02,41.232 ; 56.02,41.232 RN_M1.1@56.02,43.802 ; 56.02,41.232 RN_M1.1@56.02,43.802 ; 56.02,41.232 RN_M1.1@56.02,43.802 ; 56.02,41.232 RN_M1.1@56.02,43.802
NetRN_M1_2: RN_M1.2 U_DR_M1.13 | length 12.9
  Bottom Layer w0.114: U_DR_M1.13@57.803,39.591 57.031,39.591 55.22,41.403 ; 55.22,41.403 RN_M1.2@55.22,43.802 ; 55.22,41.403 RN_M1.2@55.22,43.802 ; 55.22,41.403 RN_M1.2@55.22,43.802 ; 55.22,41.403 RN_M1.2@55.22,43.802
NetRN_M1_3: RN_M1.3 U_DR_M1.3 | length 14.9
  Bottom Layer w0.114: U_DR_M1.3@52.103,38.941 52.503,38.941 54.42,40.858 ; 54.42,40.858 RN_M1.3@54.42,43.802 ; 54.42,40.858 RN_M1.3@54.42,43.802 ; 54.42,40.858 RN_M1.3@54.42,43.802 ; 54.42,40.858 RN_M1.3@54.42,43.802
NetRN_M1_4: RN_M1.4 U_DR_M1.5 | length 10.5
  Bottom Layer w0.114: U_DR_M1.5@52.103,40.241 53.292,40.241 53.702,40.651 53.702,41.876 53.62,41.958 ; 53.62,41.958 RN_M1.4@53.62,43.802 ; 53.62,41.958 RN_M1.4@53.62,43.802 ; 53.62,41.958 RN_M1.4@53.62,43.802 ; 53.62,41.958 RN_M1.4@53.62,43.802
NetRN_M2_1: RN_M2.1 U_DR_M2.11
NetRN_M2_2: RN_M2.2 U_DR_M2.13
NetRN_M2_3: RN_M2.3 U_DR_M2.3
NetRN_M2_4: RN_M2.4 U_DR_M2.5
NetRN_M3_1: RN_M3.1 U_DR_M3.11
NetRN_M3_2: RN_M3.2 U_DR_M3.13
NetRN_M3_3: RN_M3.3 U_DR_M3.3
NetRN_M3_4: RN_M3.4 U_DR_M3.5
NetRN_M4_1: RN_M4.1 U_DR_M4.11
NetRN_M4_2: RN_M4.2 U_DR_M4.13
NetRN_M4_3: RN_M4.3 U_DR_M4.3
NetRN_M4_4: RN_M4.4 U_DR_M4.5
NetRN_M5_1: RN_M5.1 U_DR_M5.11
NetRN_M5_2: RN_M5.2 U_DR_M5.13
NetRN_M5_3: RN_M5.3 U_DR_M5.3
NetRN_M5_4: RN_M5.4 U_DR_M5.5
NetRN_M6_1: RN_M6.1 U_DR_M6.11
NetRN_M6_2: RN_M6.2 U_DR_M6.13
NetRN_M6_3: RN_M6.3 U_DR_M6.3
NetRN_M6_4: RN_M6.4 U_DR_M6.5
NetRN_M7_1: RN_M7.1 U_DR_M7.11
NetRN_M7_2: RN_M7.2 U_DR_M7.13
NetRN_M7_3: RN_M7.3 U_DR_M7.3
NetRN_M7_4: RN_M7.4 U_DR_M7.5
NetRN_M8_1: RN_M8.1 U_DR_M8.11
NetRN_M8_2: RN_M8.2 U_DR_M8.13
NetRN_M8_3: RN_M8.3 U_DR_M8.3
NetRN_M8_4: RN_M8.4 U_DR_M8.5
NetRN_M9_1: RN_M9.1 U_DR_M9.11
NetRN_M9_2: RN_M9.2 U_DR_M9.13
NetRN_M9_3: RN_M9.3 U_DR_M9.3
NetRN_M9_4: RN_M9.4 U_DR_M9.5
NetRN_M10_1: RN_M10.1 U_DR_M10.11
NetRN_M10_2: RN_M10.2 U_DR_M10.13
NetRN_M10_3: RN_M10.3 U_DR_M10.3
NetRN_M10_4: RN_M10.4 U_DR_M10.5
P1: J1.A1
P3: J1.C1
P5: J1.E1
P7: J1.A2
P9: J1.C2
P11: J1.E2
P14: J1.B3
P16: J1.D3
P18: J1.F3
P20: J1.B4
P22: J1.D4
P24: J1.F4
P25: J1.A5
P27: J1.C5
P29: J1.E5
P31: J1.A6
P32: J1.B6
P33: J1.C6
P34: J1.D6
P35: J1.E6
P37: J1.A7
P38: J1.B7
P42: J1.F7
P43: J1.A8
P51: J1.C9
P59: J1.E10
P63: J1.C11
P68: J1.B12
P69: J1.C12
P73: J1.A13
P74: J1.B13
P76: J1.D13
P77: J1.E13
P79: J1.A14
P81: J1.C14
P82: J1.D14
P84: J1.F14
P87: J1.C15
P233: J1.E39
P234: J1.F39
P236: J1.B40
P238: J1.D40
P239: J1.E40
P240: J1.F40
SLO_M1_N: J_ENC_M1.4 J_MD_M1.4 R2_M1.2 U_DR_M1.7 | length 40.7
  Top Layer w0.114: v2(51.816,29.896) 52.852,29.896 J_ENC_M1.4@52.885,29.863 53.36,29.863 53.603,30.106 53.603,30.175 53.67,30.242 53.924,30.242 53.936,30.23 56.96,33.254 56.96,34.974 56.567,35.367 56.56,35.367 54.552,37.375 54.552,40.802 54.101,41.253 54.101,41.462 R2_M1.2@53.92,41.642 ; J_MD_M1.4@52.946,14.106 52.471,14.106 52.229,14.349 52.229,14.419 52.161,14.486 51.908,14.486 51.568,14.826 51.568,19.024 52.228,19.684 53.441,19.684 53.848,20.091 53.848,21.228 53.68,21.396 v2(53.68,21.463) ; v2(53.115,41.529) 53.146,41.529 53.349,41.326 53.601,41.326 53.672,41.396 53.672,41.462 53.864,41.654 R2_M1.2@53.886,41.654 53.908,41.654 R2_M1.2@53.92,41.642 ; R2_M1.2@53.898,41.642 R2_M1.2@53.92,41.642
  Bottom Layer w0.114: v2(51.816,29.896) 51.88,29.96 51.88,30.142 51.97,30.232 52.065,30.232 53.848,28.45 53.848,21.698 53.68,21.53 v2(53.68,21.463) ; U_DR_M1.7@52.047,41.551 U_DR_M1.7@52.058,41.54 ; v2@53.137,41.529 v2@53.126,41.54 ; U_DR_M1.7@52.058,41.54 v2@53.126,41.54 ; U_DR_M1.7@52.058,41.54 v2@53.126,41.54 ; U_DR_M1.7@52.058,41.54 v2@53.126,41.54
SLO_M1_P: J_ENC_M1.3 J_MD_M1.3 R2_M1.1 U_DR_M1.6 | length 39.5
  Top Layer w0.114: v2(51.793,30.81) 52.832,30.81 J_ENC_M1.3@52.885,30.863 53.36,30.863 53.603,30.62 53.603,30.551 53.67,30.484 53.824,30.484 53.836,30.472 56.718,33.354 56.718,34.874 56.706,34.874 56.706,34.886 56.467,35.125 56.46,35.125 54.31,37.275 54.31,40.542 54.243,40.609 54.031,40.609 R2_M1.1@53.886,40.754 53.864,40.754 53.672,40.947 53.672,41.013 53.612,41.073 ; J_MD_M1.3@52.946,15.106 52.471,15.106 52.229,14.864 52.229,14.794 52.161,14.727 52.008,14.727 51.809,14.926 51.809,18.924 52.328,19.443 53.541,19.443 54.09,19.991 54.09,21.228 54.257,21.396 v2(54.257,21.463) ; v2@53.114,40.869 v2@53.146,40.869 ; v2@53.134,40.881 53.337,41.084 53.349,41.073 53.612,41.073 ; 53.6,41.084 53.612,41.073
  Bottom Layer w0.114: v2(51.793,30.81) 51.858,30.746 51.858,30.587 51.97,30.474 52.165,30.474 54.09,28.55 54.09,21.698 54.257,21.53 v2(54.257,21.463) ; U_DR_M1.6@52.047,40.901 52.057,40.891 U_DR_M1.6@52.069,40.879 ; v2@53.114,40.891 v2@53.124,40.881 ; U_DR_M1.6@52.069,40.879 v2@53.126,40.879 ; U_DR_M1.6@52.069,40.879 v2@53.126,40.879 ; U_DR_M1.6@52.069,40.879 v2@53.126,40.879
  other v2: 53.102,40.881
SLO_M2_N: J_ENC_M2.4 J_MD_M2.4 R2_M2.2 U_DR_M2.7
SLO_M2_P: J_ENC_M2.3 J_MD_M2.3 R2_M2.1 U_DR_M2.6
SLO_M3_N: J_ENC_M3.4 J_MD_M3.4 R2_M3.2 U_DR_M3.7
SLO_M3_P: J_ENC_M3.3 J_MD_M3.3 R2_M3.1 U_DR_M3.6
SLO_M4_N: J_ENC_M4.4 J_MD_M4.4 R2_M4.2 U_DR_M4.7
SLO_M4_P: J_ENC_M4.3 J_MD_M4.3 R2_M4.1 U_DR_M4.6
SLO_M5_N: J_ENC_M5.4 J_MD_M5.4 R2_M5.2 U_DR_M5.7
SLO_M5_P: J_ENC_M5.3 J_MD_M5.3 R2_M5.1 U_DR_M5.6
SLO_M6_N: J_ENC_M6.4 J_MD_M6.4 R2_M6.2 U_DR_M6.7
SLO_M6_P: J_ENC_M6.3 J_MD_M6.3 R2_M6.1 U_DR_M6.6
SLO_M7_N: J_ENC_M7.4 J_MD_M7.4 R2_M7.2 U_DR_M7.7
SLO_M7_P: J_ENC_M7.3 J_MD_M7.3 R2_M7.1 U_DR_M7.6
SLO_M8_N: J_ENC_M8.4 J_MD_M8.4 R2_M8.2 U_DR_M8.7
SLO_M8_P: J_ENC_M8.3 J_MD_M8.3 R2_M8.1 U_DR_M8.6
SLO_M9_N: J_ENC_M9.4 J_MD_M9.4 R2_M9.2 U_DR_M9.7
SLO_M9_P: J_ENC_M9.3 J_MD_M9.3 R2_M9.1 U_DR_M9.6
SLO_M10_N: J_ENC_M10.4 J_MD_M10.4 R2_M10.2 U_DR_M10.7
SLO_M10_P: J_ENC_M10.3 J_MD_M10.3 R2_M10.1 U_DR_M10.6
STO+_M1: J-ESTOP.1 J_MD_M1.5 J_MD_M2.5 J_MD_M3.5 J_MD_M4.5 J_MD_M5.5 J_MD_M6.5 J_MD_M7.5 J_MD_M8.5 J_MD_M9.5 J_MD_M10.5
STO-_M1: J-ESTOP.2 J_MD_M1.6 J_MD_M2.6 J_MD_M3.6 J_MD_M4.6 J_MD_M5.6 J_MD_M6.6 J_MD_M7.6 J_MD_M8.6 J_MD_M9.6 J_MD_M10.6
pads on no net: J1. J-ESTOP.3 J-ESTOP.4 J_5VIN.3 J_5VIN.4 J_AO.21 J_AO.22 J_D15.3 J_D15.13 J_ENC_M1.11 J_ENC_M1.12 J_ENC_M2.11 J_ENC_M2.12 J_ENC_M3.11 J_ENC_M3.12 J_ENC_M4.11 J_ENC_M4.12 J_ENC_M5.11 J_ENC_M5.12 J_ENC_M6.11 J_ENC_M6.12 J_ENC_M7.11 J_ENC_M7.12 J_ENC_M8.11 J_ENC_M8.12 J_ENC_M9.11 J_ENC_M9.12 J_ENC_M10.11 J_ENC_M10.12 J_MD_M1.9 J_MD_M1.10 J_MD_M2.9 J_MD_M2.10 J_MD_M3.9 J_MD_M3.10 J_MD_M4.9 J_MD_M4.10 J_MD_M5.9 J_MD_M5.10 J_MD_M6.9 J_MD_M6.10 J_MD_M7.9 J_MD_M7.10 J_MD_M8.9 J_MD_M8.10 J_MD_M9.9 J_MD_M9.10 J_MD_M10.9 J_MD_M10.10 U_DR_M1.4 U_DR_M2.4 U_DR_M3.4 U_DR_M4.4 U_DR_M5.4 U_DR_M6.4 U_DR_M7.4 U_DR_M8.4 U_DR_M9.4 U_DR_M10.4

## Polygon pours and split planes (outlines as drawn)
5V_M1 on Top Layer "5V_M1_L01_P013" (solid, pour order 13): 24.994,93.447 30.226,93.447 30.226,91.973 27.254,89.002 11.633,89.002 8.915,86.284 8.915,78.867 6.401,78.867 6.401,91.542 23.343,91.542
5V_C_SERIES on Top Layer "Top Layer-5V_IN" (solid, pour order 6): 32.893,98.171 33.655,98.171 34.036,98.552 34.036,99.314 34.798,99.314 35.306,99.822 35.306,105.512 37.719,107.925 115.799,107.925 123.546,100.178 123.546,97.155 132.385,97.155 132.436,97.206 132.131,97.511 132.131,105.156 125.806,111.481 35.306,111.506 35.305,111.506 34.925,111.506 32.893,111.506
GND on Top Layer "GND_L01_P010" (solid, pour order 10): 136.271,102.743 136.271,101.092 141.478,101.092 141.478,102.616 141.351,102.743
5V_FILT on Top Layer "5V_FILT_L01_P009" (solid, pour order 9): 134.264,100.533 134.391,100.66 140.665,100.66 140.665,97.841 137.389,94.564 137.389,80.493 136.347,79.451 132.715,79.451 132.131,80.035 132.131,85.547 134.264,87.681
GND on Top Layer "GND_L01_P003" (solid, pour order 3): 125.349,90.246 129.54,90.246 132.207,92.913 132.207,94.717 128.067,94.717 127.457,94.107 125.349,94.107
GND on Top Layer "GND_L01_P000" (solid, pour order 0): 0.356,102.235 5.791,102.235 5.791,64.897 0.356,64.897
GND on Mid Layer 1 (split plane): 153.16,102.532 153.16,0.511 0.51,0.637 0.51,112.52 143.172,112.52
GND on Mid Layer 2 (split plane): 153.16,102.532 153.16,0.511 0.51,0.637 0.51,112.52 143.172,112.52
